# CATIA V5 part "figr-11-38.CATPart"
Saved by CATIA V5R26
Part number: Part1
Bounding box of the stored display mesh (mm): x -177 to 59, y -180 to 60, z 0 to 80
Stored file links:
  D:\_Deepak\CATIA\CATIA V5-6R2016_Deepak\Resources\Part files\Partfiles\c11_catia_v5_6r2016_prt\figr-11-38.CATPart
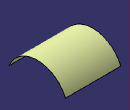
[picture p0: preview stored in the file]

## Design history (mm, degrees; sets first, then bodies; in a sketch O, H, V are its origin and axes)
Set1
  Extrude1: Element1 Sketch1, Lim1 59, Lim2 59, Direction yz-plane
  Scaling1: ToTransfor Extrude1, Reference vertex [face of Extrude1], Ratio 2
Body1 (main body)
  Sketch1 on yz-plane, origin (0, 0, 0), H (0, 1, 0), V (0, 0, 1)
    arc A1 centre (0, -25) radius 65 from (-60, 0) to (60, 0) cw
    point P2 (-60, 0)
    point P3 (60, 0)
    coincidence: P2 H, P3 H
